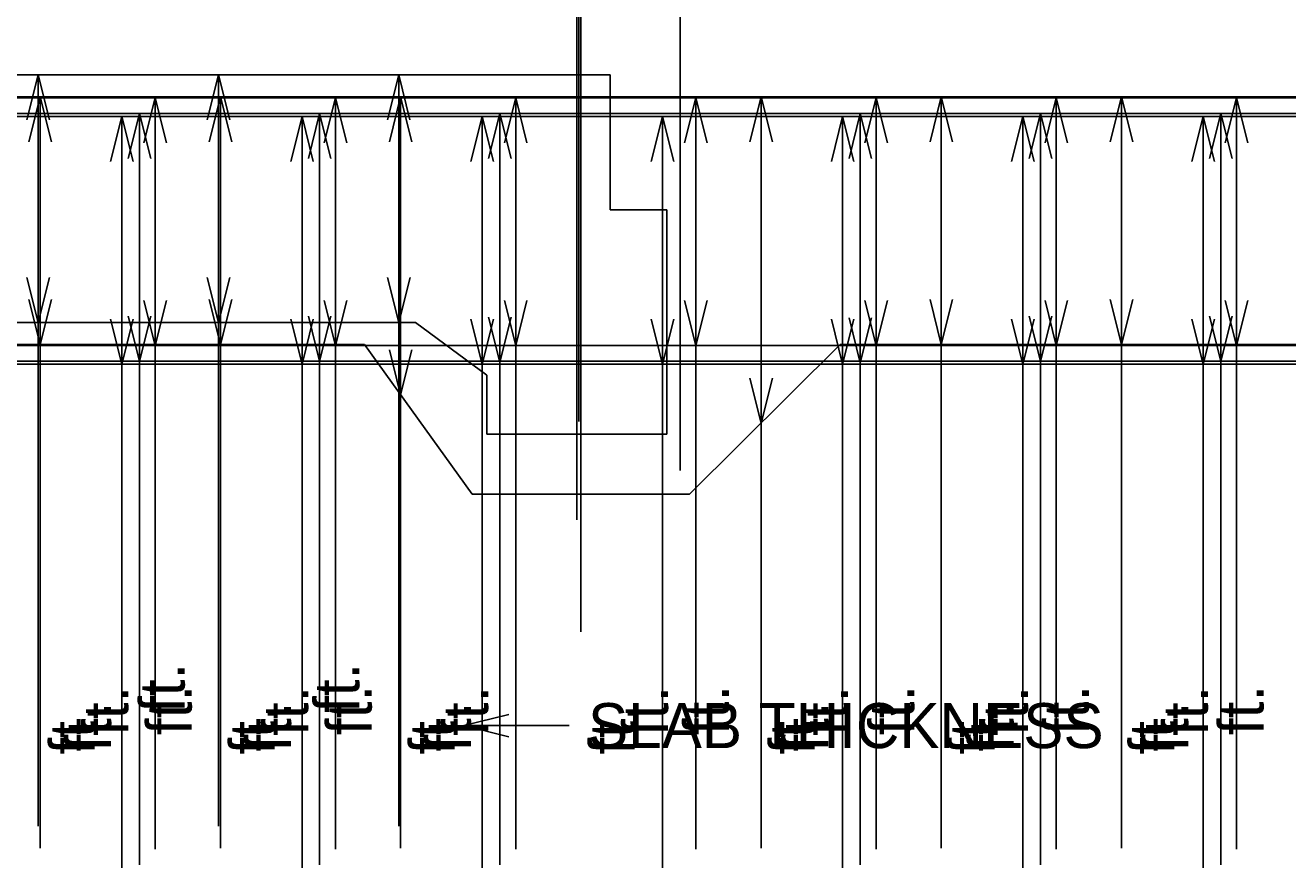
# Model space of a CAD drawing. Extents: x -6.7 to 29.5, y -5.1 to 20.6.
# Drawn here: x 5.72 to 9.223, y 12.449 to 14.787 of the extents above; entities that cross this region are included whole.
import ezdxf

# ---------------------------------------------------------------- set-up
doc = ezdxf.new("R2010")
doc.units = 0
for name, color, linetype in [('Level 5', 7, 'Continuous'), ('Level 6', 7, 'Continuous'), ('Level 7', 7, 'Continuous'), ('Level 8', 7, 'Continuous'), ('Level 9', 7, 'Continuous')]:
    doc.layers.add(name, color=color, linetype=linetype)

msp = doc.modelspace()

# ---------------------------------------------------------------- linework, layer by layer
at = {"layer": 'Level 5'}
for p, q in [((7.2506, 15.9648), (7.2506, 13.4142)), ((7.2511, 15.9707), (7.2511, 13.6584)), ((7.2564, 15.9707), (7.2564, 13.6874)), ((2.1636, 14.6495), (7.3436, 14.6495)), ((5.7564, 13.962), (5.7564, 14.6495)), ((5.8189, 14.6495), (5.8189, 14.6495)), ((6.2564, 13.8595), (6.2564, 14.6495)), ((6.3189, 14.6495), (6.3189, 14.6495)), ((6.6939, 14.6495), (6.6939, 14.6495)), ((6.7564, 13.5244), (6.7564, 14.6495)), ((6.8189, 14.6495), (6.8189, 14.6495)), ((7.3436, 14.6495), (7.3436, 14.2745)), ((7.3436, 14.2745), (7.5006, 14.2745)), ((7.5006, 14.2745), (7.5006, 13.6518)), ((2.704, 13.962), (6.8033, 13.962)), ((5.7564, 12.5639), (5.7564, 13.962)), ((5.8189, 13.962), (5.8189, 13.962)), ((6.8033, 13.962), (7.0006, 13.8154)), ((6.2564, 12.5639), (6.2564, 13.8595)), ((7.0006, 13.8154), (7.0006, 13.6518)), ((7.5006, 13.6518), (7.0006, 13.6518)), ((6.7564, 12.5639), (6.7564, 13.5244)), ((6.9368, 12.843), (7.229, 12.843))]:
    msp.add_line(p, q, dxfattribs=at)
for points in [[(5.7252, 14.5245), (5.7564, 14.6495), (5.7877, 14.5245)], [(6.2252, 14.5245), (6.2564, 14.6495), (6.2877, 14.5245)], [(6.7877, 14.5245), (6.7564, 14.6495), (6.7252, 14.5245)], [(5.7877, 14.087), (5.7564, 13.962), (5.7252, 14.087)], [(6.2877, 14.087), (6.2564, 13.962), (6.2252, 14.087)], [(6.7255, 14.087), (6.7567, 13.962), (6.788, 14.087)], [(7.0618, 12.8118), (6.9368, 12.843), (7.0618, 12.8743)]]:
    msp.add_lwpolyline(points, dxfattribs=at)
at = {"layer": 'Level 6'}
for p, q in [((-0.0118, 14.5857), (10.1735, 14.5857)), ((6.081, 13.8982), (6.081, 14.5857)), ((6.1435, 14.5857), (6.1435, 14.5857)), ((6.581, 13.8982), (6.581, 14.5857)), ((6.6435, 14.5857), (6.6435, 14.5857)), ((7.081, 13.8982), (7.081, 14.5857)), ((7.1435, 14.5857), (7.1435, 14.5857)), ((7.581, 13.8982), (7.581, 14.5857)), ((7.6435, 14.5857), (7.6435, 14.5857)), ((8.081, 13.8982), (8.081, 14.5857)), ((8.1435, 14.5857), (8.1435, 14.5857)), ((8.581, 13.8982), (8.581, 14.5857)), ((8.6435, 14.5857), (8.6435, 14.5857)), ((9.081, 13.8982), (9.081, 14.5857)), ((9.1435, 14.5857), (9.1435, 14.5857)), ((5.081, 13.8982), (9.6332, 13.8982)), ((6.081, 12.5001), (6.081, 13.8982)), ((6.1435, 13.8982), (6.1435, 13.8982)), ((6.581, 12.5001), (6.581, 13.8982)), ((6.6435, 13.8982), (6.6435, 13.8982)), ((7.081, 12.5001), (7.081, 13.8982)), ((7.1435, 13.8982), (7.1435, 13.8982)), ((7.581, 12.5001), (7.581, 13.8982)), ((7.6435, 13.8982), (7.6435, 13.8982)), ((8.081, 12.5001), (8.081, 13.8982)), ((8.1435, 13.8982), (8.1435, 13.8982)), ((8.581, 12.5001), (8.581, 13.8982)), ((8.6435, 13.8982), (8.6435, 13.8982)), ((9.081, 12.5001), (9.081, 13.8982)), ((9.1435, 13.8982), (9.1435, 13.8982))]:
    msp.add_line(p, q, dxfattribs=at)
for points in [[(6.0498, 14.4607), (6.081, 14.5857), (6.1123, 14.4607)], [(6.5498, 14.4607), (6.581, 14.5857), (6.6123, 14.4607)], [(7.0498, 14.4607), (7.081, 14.5857), (7.1123, 14.4607)], [(7.5498, 14.4607), (7.581, 14.5857), (7.6123, 14.4607)], [(8.0498, 14.4607), (8.081, 14.5857), (8.1123, 14.4607)], [(8.5498, 14.4607), (8.581, 14.5857), (8.6123, 14.4607)], [(9.0498, 14.4607), (9.081, 14.5857), (9.1123, 14.4607)], [(6.1123, 14.0232), (6.081, 13.8982), (6.0498, 14.0232)], [(6.6123, 14.0232), (6.581, 13.8982), (6.5498, 14.0232)], [(7.1123, 14.0232), (7.081, 13.8982), (7.0498, 14.0232)], [(7.6123, 14.0232), (7.581, 13.8982), (7.5498, 14.0232)], [(8.1123, 14.0232), (8.081, 13.8982), (8.0498, 14.0232)], [(8.6123, 14.0232), (8.581, 13.8982), (8.5498, 14.0232)], [(9.1123, 14.0232), (9.081, 13.8982), (9.0498, 14.0232)]]:
    msp.add_lwpolyline(points, dxfattribs=at)
at = {"layer": 'Level 7'}
for p, q in [((7.5372, 15.8636), (7.5372, 13.5513)), ((-2.5556, 14.5424), (12.6301, 14.5424)), ((6.0372, 13.8549), (6.0372, 14.5424)), ((6.0997, 14.5424), (6.0997, 14.5424)), ((6.5372, 13.8549), (6.5372, 14.5424)), ((6.5997, 14.5424), (6.5997, 14.5424)), ((7.0372, 13.5484), (7.0372, 14.5424)), ((7.0997, 14.5424), (7.0997, 14.5424)), ((8.0372, 13.4173), (8.0372, 14.5424)), ((8.0997, 14.5424), (8.0997, 14.5424)), ((8.5372, 13.6878), (8.5372, 14.5424)), ((8.5997, 14.5424), (8.5997, 14.5424)), ((9.0372, 13.8549), (9.0372, 14.5424)), ((9.0997, 14.5424), (9.0997, 14.5424)), ((2.5372, 13.8549), (7.5372, 13.8549)), ((6.0372, 12.4568), (6.0372, 13.8549)), ((6.0997, 13.8549), (6.0997, 13.8549)), ((6.5372, 12.4568), (6.5372, 13.8549)), ((6.5997, 13.8549), (6.5997, 13.8549)), ((7.5372, 13.8549), (12.0897, 13.8549)), ((9.0372, 12.4568), (9.0372, 13.8549)), ((9.0997, 13.8549), (9.0997, 13.8549)), ((8.5372, 12.4568), (8.5372, 13.6878)), ((7.0372, 12.4568), (7.0372, 13.5484)), ((8.0372, 12.4568), (8.0372, 13.4173))]:
    msp.add_line(p, q, dxfattribs=at)
for points in [[(6.006, 14.4174), (6.0372, 14.5424), (6.0685, 14.4174)], [(6.506, 14.4174), (6.5372, 14.5424), (6.5685, 14.4174)], [(7.006, 14.4174), (7.0372, 14.5424), (7.0685, 14.4174)], [(8.006, 14.4174), (8.0372, 14.5424), (8.0685, 14.4174)], [(8.506, 14.4174), (8.5372, 14.5424), (8.5685, 14.4174)], [(9.006, 14.4174), (9.0372, 14.5424), (9.0685, 14.4174)], [(6.0685, 13.9799), (6.0372, 13.8549), (6.006, 13.9799)], [(6.5685, 13.9799), (6.5372, 13.8549), (6.506, 13.9799)], [(7.0685, 13.9766), (7.0372, 13.8516), (7.006, 13.9766)], [(8.5685, 13.9799), (8.5372, 13.8549), (8.506, 13.9799)], [(9.0685, 13.9799), (9.0372, 13.8549), (9.006, 13.9799)], [(8.0685, 13.9747), (8.0372, 13.8497), (8.006, 13.9747)]]:
    msp.add_lwpolyline(points, dxfattribs=at)
at = {"layer": 'Level 8'}
for p, q in [((-0.1047, 14.5341), (10.0808, 14.5341)), ((5.9882, 13.8466), (5.9882, 14.5341)), ((6.0507, 14.5341), (6.0507, 14.5341)), ((6.4882, 13.8466), (6.4882, 14.5341)), ((6.5507, 14.5341), (6.5507, 14.5341)), ((6.9882, 13.8466), (6.9882, 14.5341)), ((7.0507, 14.5341), (7.0507, 14.5341)), ((7.4882, 13.8466), (7.4882, 14.5341)), ((7.5507, 14.5341), (7.5507, 14.5341)), ((7.9882, 13.8466), (7.9882, 14.5341)), ((8.0507, 14.5341), (8.0507, 14.5341)), ((8.4882, 13.8466), (8.4882, 14.5341)), ((8.5507, 14.5341), (8.5507, 14.5341)), ((8.9882, 13.8466), (8.9882, 14.5341)), ((9.0507, 14.5341), (9.0507, 14.5341)), ((5.5887, 13.8466), (9.5404, 13.8466)), ((5.9882, 12.4485), (5.9882, 13.8466)), ((6.0507, 13.8466), (6.0507, 13.8466)), ((6.4882, 12.4485), (6.4882, 13.8466)), ((6.5507, 13.8466), (6.5507, 13.8466)), ((6.9882, 12.4485), (6.9882, 13.8466)), ((7.0507, 13.8466), (7.0507, 13.8466)), ((7.4882, 12.4485), (7.4882, 13.8466)), ((7.5507, 13.8466), (7.5507, 13.8466)), ((7.9882, 12.4485), (7.9882, 13.8466)), ((8.0507, 13.8466), (8.0507, 13.8466)), ((8.4882, 12.4485), (8.4882, 13.8466)), ((8.5507, 13.8466), (8.5507, 13.8466)), ((8.9882, 12.4485), (8.9882, 13.8466)), ((9.0507, 13.8466), (9.0507, 13.8466))]:
    msp.add_line(p, q, dxfattribs=at)
for points in [[(5.9569, 14.4091), (5.9882, 14.5341), (6.0194, 14.4091)], [(6.4569, 14.4091), (6.4882, 14.5341), (6.5194, 14.4091)], [(6.9569, 14.4091), (6.9882, 14.5341), (7.0194, 14.4091)], [(7.4569, 14.4091), (7.4882, 14.5341), (7.5194, 14.4091)], [(7.9569, 14.4091), (7.9882, 14.5341), (8.0194, 14.4091)], [(8.4569, 14.4091), (8.4882, 14.5341), (8.5194, 14.4091)], [(8.9569, 14.4091), (8.9882, 14.5341), (9.0194, 14.4091)], [(6.0194, 13.9716), (5.9882, 13.8466), (5.9569, 13.9716)], [(6.5194, 13.9716), (6.4882, 13.8466), (6.4569, 13.9716)], [(7.0194, 13.9716), (6.9882, 13.8466), (6.9569, 13.9716)], [(7.5194, 13.9716), (7.4882, 13.8466), (7.4569, 13.9716)], [(8.0194, 13.9716), (7.9882, 13.8466), (7.9569, 13.9716)], [(8.5194, 13.9716), (8.4882, 13.8466), (8.4569, 13.9716)], [(9.0194, 13.9716), (8.9882, 13.8466), (8.9569, 13.9716)]]:
    msp.add_lwpolyline(points, dxfattribs=at)
at = {"layer": 'Level 9'}
for p, q in [((7.2619, 15.9094), (7.2619, 13.1029)), ((-2.831, 14.5882), (12.3547, 14.5882)), ((5.7619, 13.9007), (5.7619, 14.5882)), ((5.8244, 14.5882), (5.8244, 14.5882)), ((6.2619, 13.9007), (6.2619, 14.5882)), ((6.3244, 14.5882), (6.3244, 14.5882)), ((6.7619, 13.5942), (6.7619, 14.5882)), ((6.8244, 14.5882), (6.8244, 14.5882)), ((7.7619, 13.4631), (7.7619, 14.5882)), ((7.8244, 14.5882), (7.8244, 14.5882)), ((8.2619, 13.7336), (8.2619, 14.5882)), ((8.3244, 14.5882), (8.3244, 14.5882)), ((8.7619, 13.9007), (8.7619, 14.5882)), ((8.8244, 14.5882), (8.8244, 14.5882)), ((2.8624, 13.9007), (6.6614, 13.9007)), ((5.7619, 12.5026), (5.7619, 13.9007)), ((5.8244, 13.9007), (5.8244, 13.9007)), ((6.2619, 12.5026), (6.2619, 13.9007)), ((6.3244, 13.9007), (6.3244, 13.9007)), ((6.6614, 13.9007), (6.9605, 13.485)), ((7.9812, 13.9007), (7.5632, 13.485)), ((7.9812, 13.9007), (11.8144, 13.9007)), ((8.7619, 12.5026), (8.7619, 13.9007)), ((8.8244, 13.9007), (8.8244, 13.9007)), ((8.2619, 12.5026), (8.2619, 13.7336)), ((6.7619, 12.5026), (6.7619, 13.5942)), ((7.5632, 13.485), (6.9605, 13.485)), ((7.7619, 12.5026), (7.7619, 13.4631))]:
    msp.add_line(p, q, dxfattribs=at)
for points in [[(5.7306, 14.4632), (5.7619, 14.5882), (5.7931, 14.4632)], [(6.2306, 14.4632), (6.2619, 14.5882), (6.2931, 14.4632)], [(6.7306, 14.4632), (6.7619, 14.5882), (6.7931, 14.4632)], [(7.7306, 14.4632), (7.7619, 14.5882), (7.7931, 14.4632)], [(8.2306, 14.4632), (8.2619, 14.5882), (8.2931, 14.4632)], [(8.7306, 14.4632), (8.7619, 14.5882), (8.7931, 14.4632)], [(5.7931, 14.0257), (5.7619, 13.9007), (5.7306, 14.0257)], [(6.2931, 14.0257), (6.2619, 13.9007), (6.2306, 14.0257)], [(8.2931, 14.0257), (8.2619, 13.9007), (8.2306, 14.0257)], [(8.7931, 14.0257), (8.7619, 13.9007), (8.7306, 14.0257)], [(6.7931, 13.886), (6.7619, 13.761), (6.7306, 13.886)], [(7.7931, 13.8075), (7.7619, 13.6825), (7.7306, 13.8075)]]:
    msp.add_lwpolyline(points, dxfattribs=at)

# ---------------------------------------------------------------- texts
at = {"layer": 'Level 5'}
for p in [(6.1628, 12.646), (6.6473, 12.646)]:
    msp.add_text('     ft.', height=0.125, rotation=90, dxfattribs=at).set_placement(p)
msp.add_text('SLAB THICKNESS', height=0.125, dxfattribs=at).set_placement((7.2817, 12.7805))
at = {"layer": 'Level 6'}
for p in [(6.0062, 12.5822), (6.5054, 12.5822), (7.0047, 12.5822), (7.5039, 12.5822), (8.0031, 12.5822), (8.5024, 12.5822), (9.0016, 12.5822)]:
    msp.add_text('     ft.', height=0.125, rotation=90, dxfattribs=at).set_placement(p)
at = {"layer": 'Level 7'}
for p in [(5.9586, 12.5389), (6.4578, 12.5389), (6.9571, 12.5389), (7.9484, 12.5389), (8.4623, 12.5389), (8.9469, 12.5389)]:
    msp.add_text('     ft.', height=0.125, rotation=90, dxfattribs=at).set_placement(p)
at = {"layer": 'Level 8'}
for p in [(5.9133, 12.5306), (6.4125, 12.5306), (6.9118, 12.5306), (7.411, 12.5306), (7.9103, 12.5306), (8.4095, 12.5306), (8.9088, 12.5306)]:
    msp.add_text('     ft.', height=0.125, rotation=90, dxfattribs=at).set_placement(p)
at = {"layer": 'Level 9'}
for p in [(6.1824, 12.5847), (6.6817, 12.5847), (7.673, 12.5847), (8.187, 12.5847), (8.6715, 12.5847), (9.1561, 12.5847)]:
    msp.add_text('     ft.', height=0.125, rotation=90, dxfattribs=at).set_placement(p)

doc.saveas('drawing.dxf')
